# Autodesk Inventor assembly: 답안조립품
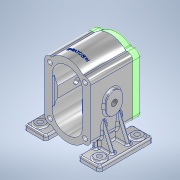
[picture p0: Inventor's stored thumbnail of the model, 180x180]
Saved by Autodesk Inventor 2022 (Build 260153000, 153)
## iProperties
Created: 2023-06
Part Number: 답안조립품
Document SubType Name: Assembly
Designer: PC-11
Author: PC-11
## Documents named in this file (3)
- C:\Users\PC-11\Desktop\730606V1016\답안조립품.iam
- C:\Users\PC-11\Desktop\730606V1016\본체.ipt
- C:\Users\PC-11\Desktop\730606V1016\뒷커버.ipt
